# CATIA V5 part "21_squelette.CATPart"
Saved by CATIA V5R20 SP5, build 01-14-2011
Part number: 21_squelette
Publications: "Point.1", "Droite.1", "Plan.4", "Plan.5", "Plan.3", "Plan.1", "Plan.2", "Point.7", "nb_trou_21_32", "Point.4", "Point.9", "Plan zx"
Bounding box of the stored display mesh (mm): x 0 to 0, y -100 to 100, z 0 to 37.5
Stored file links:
  C:\Documents and Settings\anizard\Bureau\13\21_squelette.CATPart
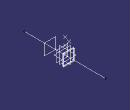
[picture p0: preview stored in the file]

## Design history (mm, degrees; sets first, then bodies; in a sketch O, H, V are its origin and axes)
Parameters
  nb_trou_21_32 = 8
Body1 (main body)
  Point1: (0, 0, 0)
  Line1: type PtDir, RefPoint Point1, Direction zx-plane, Start -100, End 100
  Plane1: type Offset, RefPlane zx-plane, Offset 7, reversed
  Plane2: type Offset, RefPlane zx-plane, Offset 37, reversed
  Point2: (0, 0, 20)
  Plane3: type Offset, RefPlane zx-plane, Offset 7.5
  Plane4: type Offset, RefPlane zx-plane, Offset 10.5
  Plane5: type Offset, RefPlane Plane1, Offset 15.75
  Point3: type OnPlane, Support Plane4, H 0, V 34, Direction (-1, 0, 0)
  Point4: type OnPlane, Support Plane4, H 0, V 34, Direction (-1, 0, 0)
  Point5: (0, 0, 37.5)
